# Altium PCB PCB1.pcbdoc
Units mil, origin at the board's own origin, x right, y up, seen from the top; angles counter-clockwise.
Board outline 2240 x 2140 mil, 2 copper layers (Top Layer, Bottom Layer); 19 components, 12 nets, 59 pads, 0 vias.
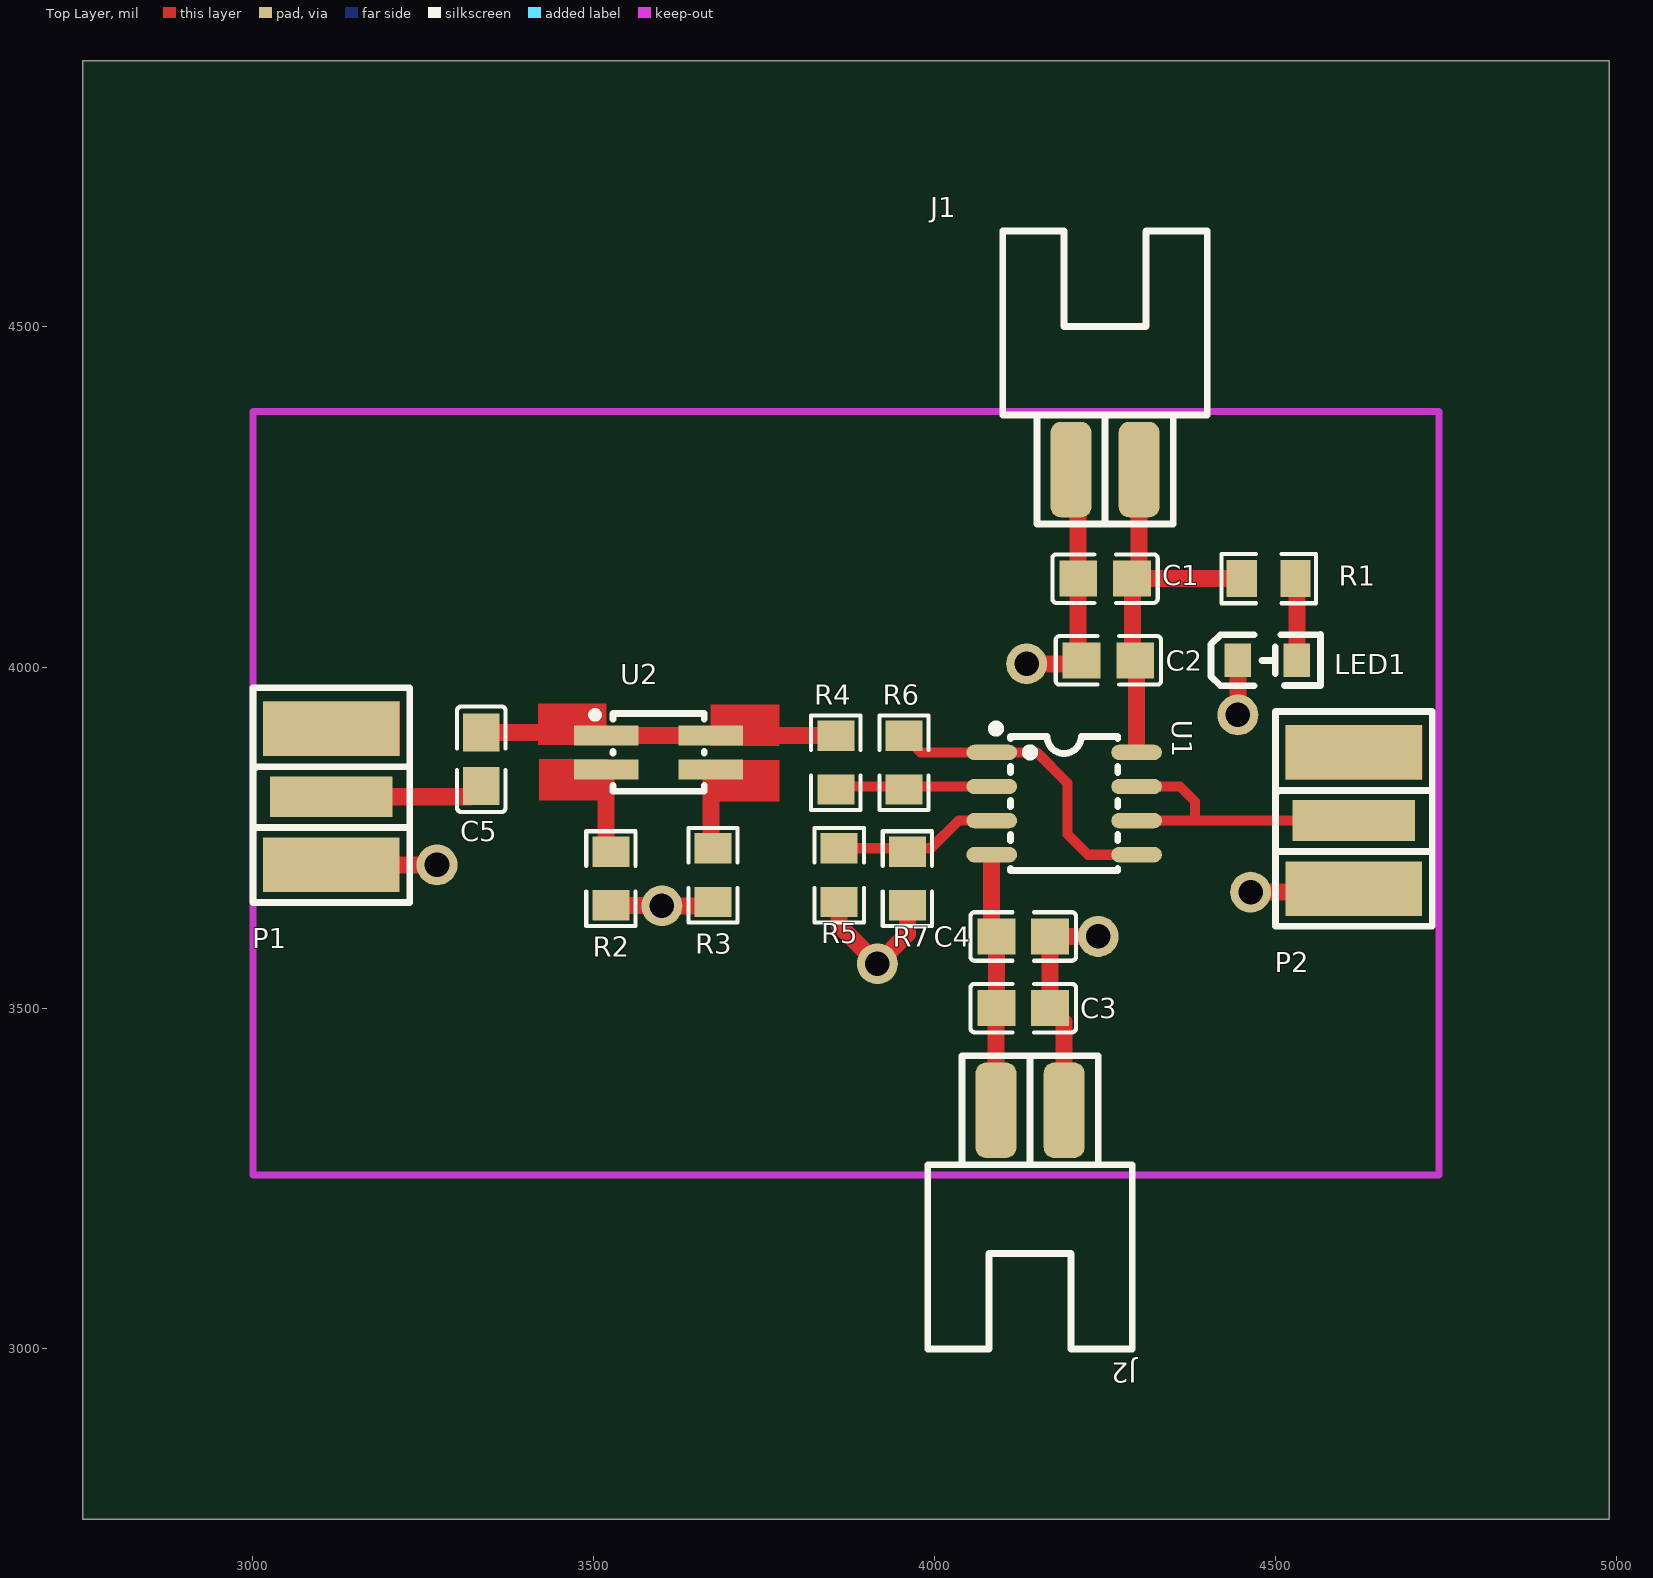
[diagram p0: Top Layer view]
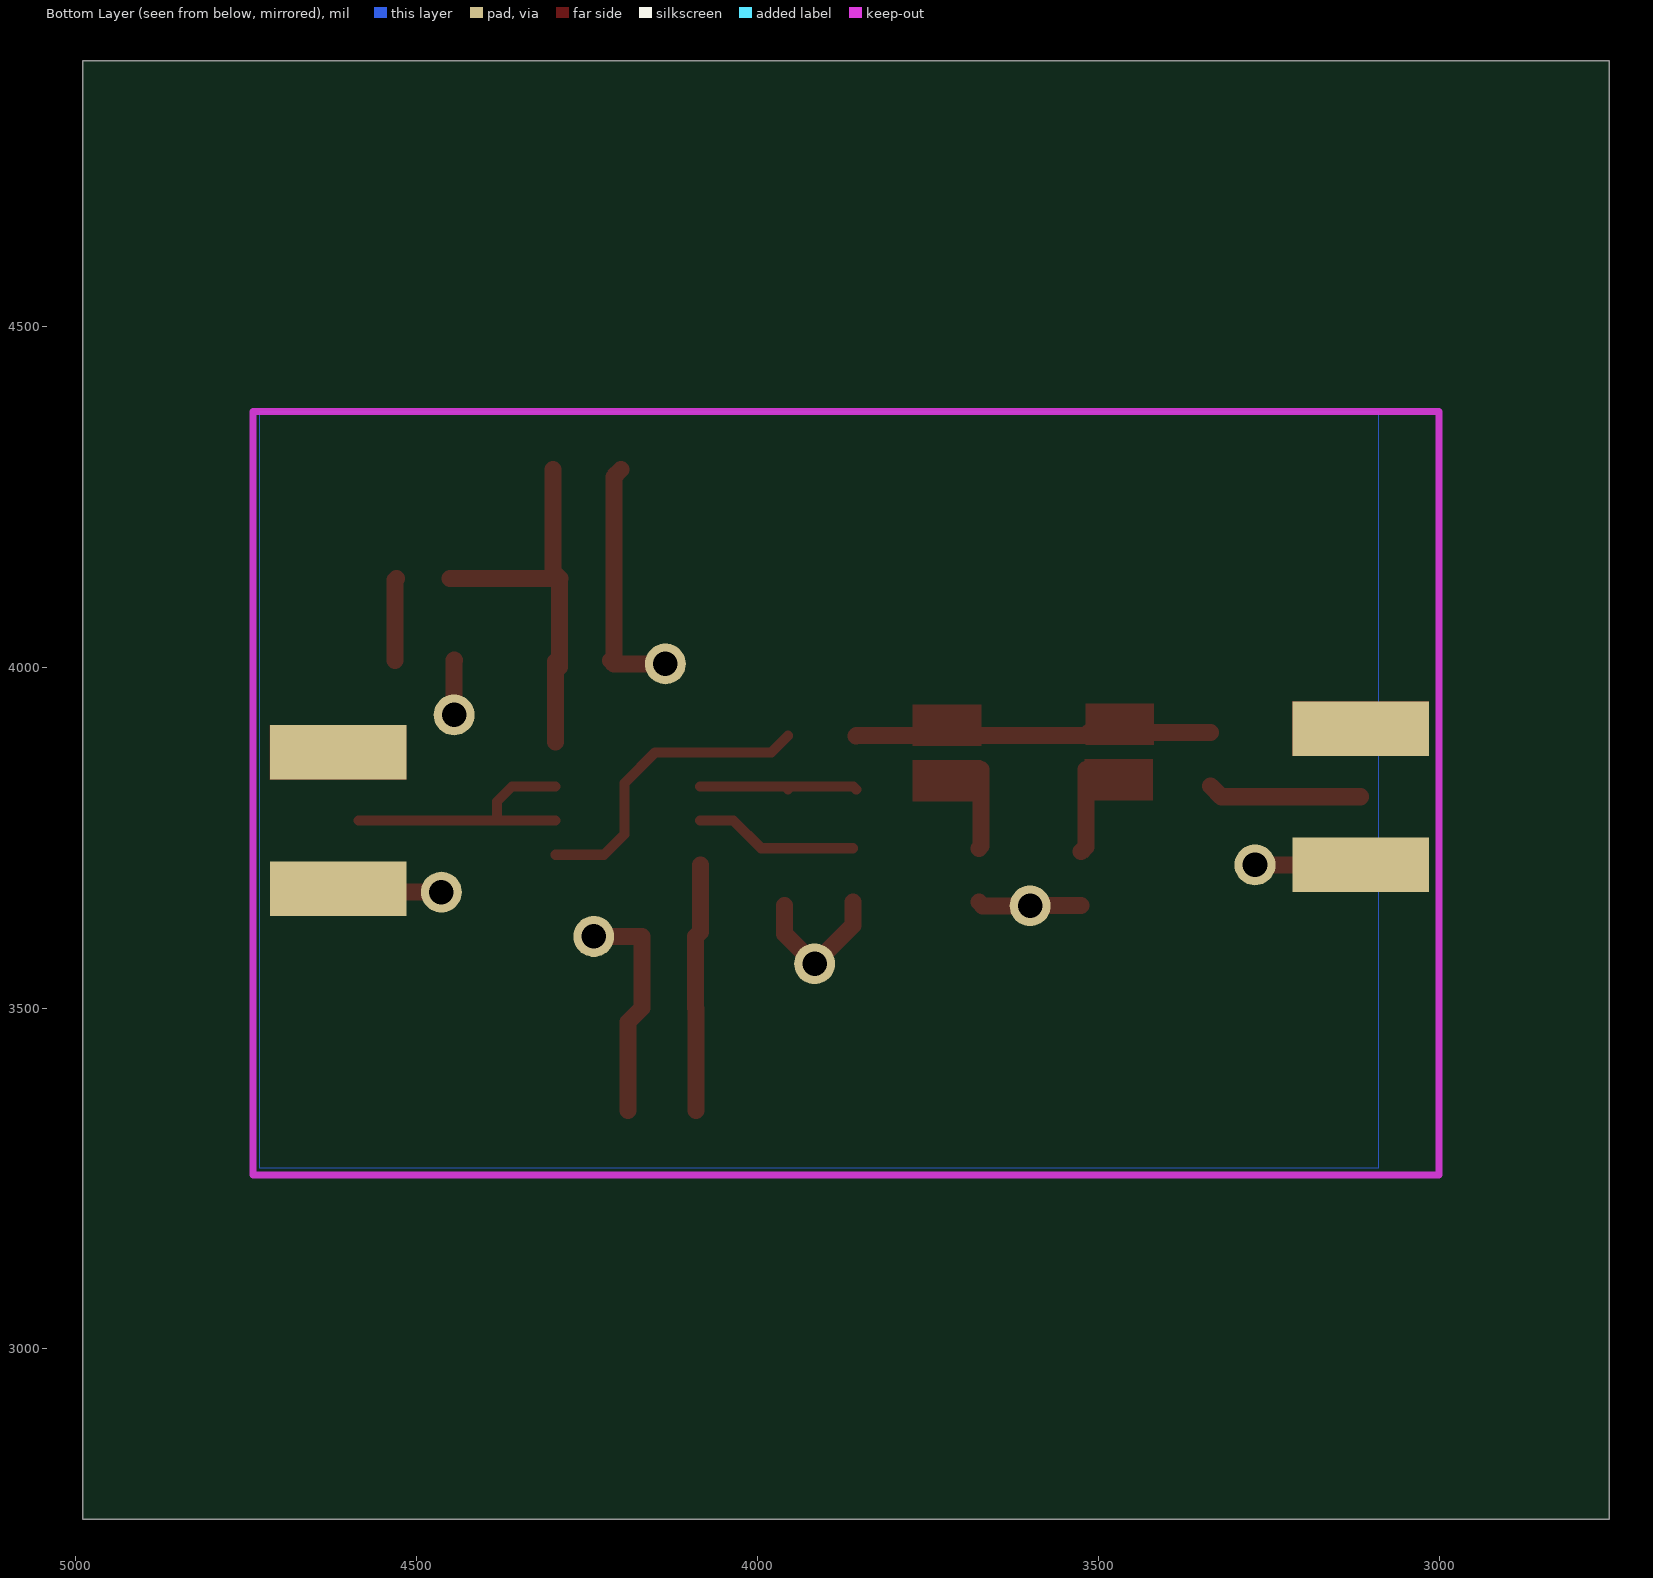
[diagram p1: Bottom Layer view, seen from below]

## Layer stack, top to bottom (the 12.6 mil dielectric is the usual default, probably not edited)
Top Layer: signal copper (thickness not stored)
Dielectric: dielectric 12.6, FR-4, Dk 4.8
Bottom Layer: signal copper (thickness not stored)

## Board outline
4990,2750 2750,2750 2750,4890 4990,4890

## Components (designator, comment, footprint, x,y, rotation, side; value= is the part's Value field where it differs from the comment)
C1 "CAP_0805" C0805 4250,4130 r180 top
C2 "CAP_0805" C0805 4255,4010 r180 top
C3 "CAP_0805" C0805 4130,3500 r180 top
C4 "CAP_0805" C0805 4130,3605 r180 top
C5 "CAP_0805" C0805 3335,3865 r90 top
J1 "CON2" sip2e 4300,4290 r0 top
J2 "CON2" sip2e 4090,3350 r180 top
LED1 "LED_0805-R" LED_0805 4490,4010 r0 top
P1 "BNC" SMA-E 3115,3810 r0 top
P2 "BNC" SMA-E 4615,3775 r0 top
R1 "Res_0805" R0805 4490,4130 r0 top
R2 "Res_0805" R0805 3525,3690 r90 top
R3 "Res_0805" R0805 3675,3695 r90 top
R4 "Res_0805" R0805 3855,3860 r270 top
R5 "Res_0805" R0805 3860,3695 r90 top
R6 "Res_0805" R0805 3955,3860 r90 top
R7 "Res_0805" R0805 3960,3690 r270 top
U1 "LT1361CS8#PBF" SO-8_L4.9-W3.9-P1.27-LS5.9-BL 4190,3800 r270 top
U2 "PZ127-2-02-S" HDR-SMD_4P-P1.27-V-M-R2-C2-LS5.3 3595,3875 r270 top

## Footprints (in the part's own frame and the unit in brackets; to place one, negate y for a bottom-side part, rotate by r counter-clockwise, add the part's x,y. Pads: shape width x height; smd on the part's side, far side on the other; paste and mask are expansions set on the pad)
C0805 [mm]
  rect 1.41x1.35 smd: 1(-1,0) 2(1,0)
  silkscreen extent -1.96,-0.9 1.96,0.9
HDR-SMD_4P-P1.27-V-M-R2-C2-LS5.3 [mm]
  rect 0.74x2.4 smd: 1(-0.635,-1.95) 2(-0.635,1.95) 3(0.635,-1.95) 4(0.635,1.95)
  silkscreen extent -1.52,-2.49 1.45,1.7
LED_0805 [mm]
  rect 1x1.25 smd: 1(-1.15,0.005) 2(1.05,0.005)
  silkscreen extent -2.15,-0.94 1.93,0.97
R0805 [mm]
  rect 1.133x1.377 smd: 1(-1,0) 2(1,0)
  silkscreen extent -1.76,-0.92 1.76,0.92
sip2e [mil]
  rrect50% 60x140 smd: 1(0,0) 2(-100,0)
  silkscreen extent -200,-80 100,350
SMA-E [mil]
  rect 180x60 smd: 1(0,0)
  rect 200x80 smd: 2(0,100) 4(0,-100)
  rect 200x80 smd far side: 3(0,100) 5(0,-100)
  Top Layer region: -100,60 100,60 100,140 -100,140
  silkscreen extent -115,-155 115,160
SO-8_L4.9-W3.9-P1.27-LS5.9-BL [mil]
  oval 22.6x74.33 smd: 1(-75,-106.26) 2(-25,-106.26) 3(25,-106.26) 4(75,-106.26) 5(75,106.26) 6(25,106.26) 7(-25,106.26) 8(-75,106.26)
  silkscreen extent -116,-106 98,79

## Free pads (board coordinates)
  round 60 hole 36: 3(3600,3650) 9(3916.1,3565) 10(3270,3710) 11(4135,4005) 11(4240,3605) 11(4445,3930) 11(4463.59,3670)

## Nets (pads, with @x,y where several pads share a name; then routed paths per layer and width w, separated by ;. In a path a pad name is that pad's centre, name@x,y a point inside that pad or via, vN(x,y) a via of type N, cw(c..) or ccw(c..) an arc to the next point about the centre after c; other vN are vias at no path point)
$1N705: LED1.2 R1.2 | length 120.6
  Top Layer w25: R1.2 4531.34,4128.03 LED1.2
$1N1104: C5.1 P1.1 | length 226.5
  Top Layer w25: P1.1 3319.37,3810 C5.1
$1N1369: C5.2 R4.1 U2.1 U2.2 | length 522.1
  Top Layer w25: C5.2 3513.86,3904.37 U2.1 U2.2 3854.37,3900 R4.1
$1N1384: R2.2 U2.3 | length 123.4
  Top Layer w25: U2.3 3518.23,3736.14 R2.2
$1N1387: R3.2 U2.4 | length 117
  Top Layer w25: U2.4 3671.77,3737.6 R3.2
$1N1400: R4.2 R6.1 U1.2 | length 236.7
  Top Layer w15: R4.2 3859.37,3825 R6.1@3959.37,3825 ; R6.1 R6.1@3959.37,3825 ; U1.2 R6.1@3959.37,3825
$1N1411: R5.2 R7.1 U1.3 | length 240.6
  Top Layer w15: R5.2 3960,3734.37 3994.37,3734.37 4035,3775 U1.3
$1N1472: R6.2 U1.1 U1.5 | length 457.4
  Top Layer w15: R6.2 3979.37,3875 U1.1 4150,3875 4195,3830 4195,3755 4225,3725 U1.5
$1N1543: P2.1 U1.6 U1.7 | length 411.6
  Top Layer w15: U1.6 4382.06,3775 ; U1.7 4360,3825 4382.06,3802.94 4382.06,3775 ; P2.1@4585,3775 4382.06,3775
+5V: C1.1 C2.1 J1.1 R1.1 U1.8 | length 576.7
  Top Layer w25: C2.1@4290,4000 4290,4129.37 C1.1 ; C2.1 4296.26,4008.11 4296.26,3890 ; J1.1 4300,4140.63 C1.1 ; R1.1 C1.1
-5V: C3.2 C4.2 J2.1 U1.4 | length 363.1
  Top Layer w25: 4083.74,3710 4083.74,3611.89 C4.2 C3.2 4090,3499.37 J2.1
GND: C1.2 C2.2 C3.1 C4.1 J1.2 J2.2 LED1.1 P1.2 P1.3 P1.4 P1.5 P2.2 P2.3 P2.4 P2.5 pad.3 pad.9 pad.10 pad.11 R2.1 R3.1 R5.1 R7.2 | length 1462.4
  Top Layer w25: P1.4 pad.10 ; R2.1 3599.37,3650.63 pad.3 3669.37,3650 R3.1 ; R5.1 3860,3621.1 pad.9 3960,3608.9 R7.2 ; pad.11@4135,4005 4210.63,4005 C2.2 4210.63,4015 C1.2 4210.63,4279.37 J1.2 ; J2.2 4190,3479.37 C3.1 C4.1 pad.11@4240,3605 ; LED1.1 4445,4009.92 pad.11@4445,3930 ; pad.11@4463.59,3670 4610,3670 P2.4

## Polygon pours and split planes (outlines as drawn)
GND on Bottom Layer (hatched 45Degree grid 30 track 10, remove dead copper, pour order 0): 3089.01,3265 4730,3265 4730,4375 3089.01,4375

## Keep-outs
Board Outline Layer:
  lines w10: 3000,3255 4740,3255 4740,4375 3000,4375 3000,3255

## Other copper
Top Layer:
  region net $1N1369: 3671.77,3885 3771.77,3885 3771.77,3945 3671.77,3945
  region net $1N1369: 3418.23,3886.18 3518.23,3886.18 3518.23,3946.18 3418.23,3946.18
  region net $1N1387: 3671.77,3803.16 3771.77,3803.16 3771.77,3863.16 3671.77,3863.16
  region net $1N1384: 3420,3805 3520,3805 3520,3865 3420,3865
